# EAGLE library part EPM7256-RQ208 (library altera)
EPM7256E MAX 7000 family
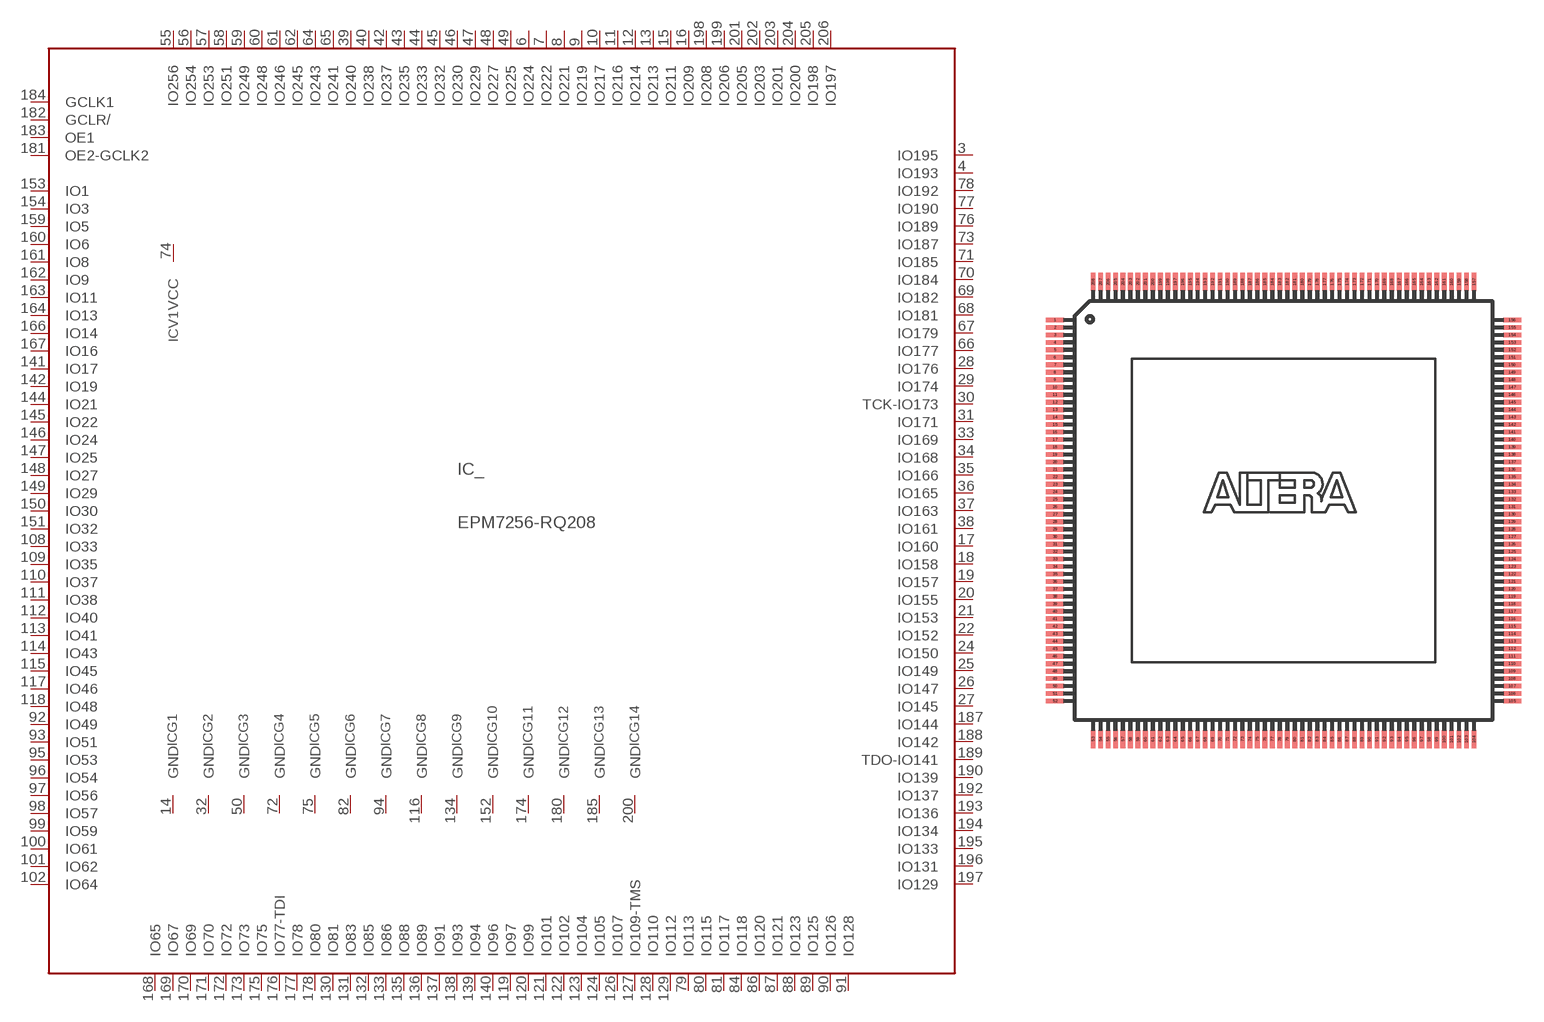
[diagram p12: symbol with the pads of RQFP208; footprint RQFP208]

Designator prefix IC; gates _=7256R208 G1=GND G2=GND G3=GND G4=GND G5=GND G6=GND G7=GND G8=GND G9=GND G10=GND G11=GND G12=GND G13=GND G14=GND V1=VCCINT V2=VCCINT V3=VCCINT V4=VCCINT VO1=VCCIO VO2=VCCIO VO3=VCCIO VO4=VCCIO VO5=VCCIO VO6=VCCIO VO7=VCCIO VO8=VCCIO VO9=VCCIO VO10=VCCIO NC1=NC NC2=NC NC3=NC NC4=NC NC5=NC NC6=NC NC7=NC NC8=NC NC9=NC NC10=NC NC11=NC NC12=NC NC13=NC NC14=NC NC15=NC NC16=NC

## EPM7256-RQ208 (MPN: EPM7256AEQC208-10N; OC_FARNELL: 1549440; OC_NEWARK: 51R9842)  [RQFP208]
1  NC1:NC  nc
2  NC2:NC  nc
3  _:IO195
4  _:IO193
5  VO1:VCCIO  pwr
6  _:IO224
7  _:IO222
8  _:IO221
9  _:IO219
10  _:IO217
11  _:IO216
12  _:IO214
13  _:IO213
14  G1:GND  pwr
15  _:IO211
16  _:IO209
17  _:IO160
18  _:IO158
19  _:IO157
20  _:IO155
21  _:IO153
22  _:IO152
23  VO2:VCCIO  pwr
24  _:IO150
25  _:IO149
26  _:IO147
27  _:IO145
28  _:IO176
29  _:IO174
30  _:TCK-IO173
31  _:IO171
32  G2:GND  pwr
33  _:IO169
34  _:IO168
35  _:IO166
36  _:IO165
37  _:IO163
38  _:IO161
39  _:IO240
40  _:IO238
41  VO3:VCCIO  pwr
42  _:IO237
43  _:IO235
44  _:IO233
45  _:IO232
46  _:IO230
47  _:IO229
48  _:IO227
49  _:IO225
50  G3:GND  pwr
51  NC3:NC  nc
52  NC4:NC  nc
53  NC5:NC  nc
54  NC6:NC  nc
55  _:IO256
56  _:IO254
57  _:IO253
58  _:IO251
59  _:IO249
60  _:IO248
61  _:IO246
62  _:IO245
63  VO4:VCCIO  pwr
64  _:IO243
65  _:IO241
66  _:IO177
67  _:IO179
68  _:IO181
69  _:IO182
70  _:IO184
71  _:IO185
72  G4:GND  pwr
73  _:IO187
74  V1:VCC  pwr
75  G5:GND  pwr
76  _:IO189
77  _:IO190
78  _:IO192
79  _:IO113
80  _:IO115
81  _:IO117
82  G6:GND  pwr
83  V2:VCC  pwr
84  _:IO118
85  VO5:VCCIO  pwr
86  _:IO120
87  _:IO121
88  _:IO123
89  _:IO125
90  _:IO126
91  _:IO128
92  _:IO49
93  _:IO51
94  G7:GND  pwr
95  _:IO53
96  _:IO54
97  _:IO56
98  _:IO57
99  _:IO59
100  _:IO61
101  _:IO62
102  _:IO64
103  NC7:NC  nc
104  NC8:NC  nc
105  NC9:NC  nc
106  NC10:NC  nc
107  VO6:VCCIO  pwr
108  _:IO33
109  _:IO35
110  _:IO37
111  _:IO38
112  _:IO40
113  _:IO41
114  _:IO43
115  _:IO45
116  G8:GND  pwr
117  _:IO46
118  _:IO48
119  _:IO97
120  _:IO99
121  _:IO101
122  _:IO102
123  _:IO104
124  _:IO105
125  VO7:VCCIO  pwr
126  _:IO107
127  _:IO109-TMS
128  _:IO110
129  _:IO112
130  _:IO81
131  _:IO83
132  _:IO85
133  _:IO86
134  G9:GND  pwr
135  _:IO88
136  _:IO89
137  _:IO91
138  _:IO93
139  _:IO94
140  _:IO96
141  _:IO17
142  _:IO19
143  VO8:VCCIO  pwr
144  _:IO21
145  _:IO22
146  _:IO24
147  _:IO25
148  _:IO27
149  _:IO29
150  _:IO30
151  _:IO32
152  G10:GND  pwr
153  _:IO1
154  _:IO3
155  NC11:NC  nc
156  NC12:NC  nc
157  NC13:NC  nc
158  NC14:NC  nc
159  _:IO5
160  _:IO6
161  _:IO8
162  _:IO9
163  _:IO11
164  _:IO13
165  VO9:VCCIO  pwr
166  _:IO14
167  _:IO16
168  _:IO65
169  _:IO67
170  _:IO69
171  _:IO70
172  _:IO72
173  _:IO73
174  G11:GND  pwr
175  _:IO75
176  _:IO77-TDI
177  _:IO78
178  _:IO80
179  V3:VCC  pwr
180  G12:GND  pwr
181  _:OE2-GCLK2  in
182  _:GCLR/  in
183  _:OE1  in
184  _:GCLK1  in
185  G13:GND  pwr
186  V4:VCC  pwr
187  _:IO144
188  _:IO142
189  _:TDO-IO141
190  _:IO139
191  VO10:VCCIO  pwr
192  _:IO137
193  _:IO136
194  _:IO134
195  _:IO133
196  _:IO131
197  _:IO129
198  _:IO208
199  _:IO206
200  G14:GND  pwr
201  _:IO205
202  _:IO203
203  _:IO201
204  _:IO200
205  _:IO198
206  _:IO197
207  NC15:NC  nc
208  NC16:NC  nc

## Footprint RQFP208 (pad centres in mm)
Power Quad Flat Pack
smd 1.2 x 0.32: 1 -15.3,12.75; 2 -15.3,12.25; 3 -15.3,11.75; 4 -15.3,11.25; 5 -15.3,10.75; 6 -15.3,10.25; 7 -15.3,9.75; 8 -15.3,9.25; 9 -15.3,8.75; 10 -15.3,8.25; 11 -15.3,7.75; 12 -15.3,7.25; 13 -15.3,6.75; 14 -15.3,6.25; 15 -15.3,5.75; 16 -15.3,5.25; 17 -15.3,4.75; 18 -15.3,4.25; 19 -15.3,3.75; 20 -15.3,3.25; 21 -15.3,2.75; 22 -15.3,2.25; 23 -15.3,1.75; 24 -15.3,1.25; 25 -15.3,0.75; 26 -15.3,0.25; 27 -15.3,-0.25; 28 -15.3,-0.75; 29 -15.3,-1.25; 30 -15.3,-1.75; 31 -15.3,-2.25; 32 -15.3,-2.75; 33 -15.3,-3.25; 34 -15.3,-3.75; 35 -15.3,-4.25; 36 -15.3,-4.75; 37 -15.3,-5.25; 38 -15.3,-5.75; 39 -15.3,-6.25; 40 -15.3,-6.75; 41 -15.3,-7.25; 42 -15.3,-7.75; 43 -15.3,-8.25; 44 -15.3,-8.75; 45 -15.3,-9.25; 46 -15.3,-9.75; 47 -15.3,-10.25; 48 -15.3,-10.75; 49 -15.3,-11.25; 50 -15.3,-11.75; 51 -15.3,-12.25; 52 -15.3,-12.75; 105 15.3,-12.75; 106 15.3,-12.25; 107 15.3,-11.75; 108 15.3,-11.25; 109 15.3,-10.75; 110 15.3,-10.25; 111 15.3,-9.75; 112 15.3,-9.25; 113 15.3,-8.75; 114 15.3,-8.25; 115 15.3,-7.75; 116 15.3,-7.25; 117 15.3,-6.75; 118 15.3,-6.25; 119 15.3,-5.75; 120 15.3,-5.25; 121 15.3,-4.75; 122 15.3,-4.25; 123 15.3,-3.75; 124 15.3,-3.25; 125 15.3,-2.75; 126 15.3,-2.25; 127 15.3,-1.75; 128 15.3,-1.25; 129 15.3,-0.75; 130 15.3,-0.25; 131 15.3,0.25; 132 15.3,0.75; 133 15.3,1.25; 134 15.3,1.75; 135 15.3,2.25; 136 15.3,2.75; 137 15.3,3.25; 138 15.3,3.75; 139 15.3,4.25; 140 15.3,4.75; 141 15.3,5.25; 142 15.3,5.75; 143 15.3,6.25; 144 15.3,6.75; 145 15.3,7.25; 146 15.3,7.75; 147 15.3,8.25; 148 15.3,8.75; 149 15.3,9.25; 150 15.3,9.75; 151 15.3,10.25; 152 15.3,10.75; 153 15.3,11.25; 154 15.3,11.75; 155 15.3,12.25; 156 15.3,12.75
smd 0.32 x 1.2: 53 -12.75,-15.3; 54 -12.25,-15.3; 55 -11.75,-15.3; 56 -11.25,-15.3; 57 -10.75,-15.3; 58 -10.25,-15.3; 59 -9.75,-15.3; 60 -9.25,-15.3; 61 -8.75,-15.3; 62 -8.25,-15.3; 63 -7.75,-15.3; 64 -7.25,-15.3; 65 -6.75,-15.3; 66 -6.25,-15.3; 67 -5.75,-15.3; 68 -5.25,-15.3; 69 -4.75,-15.3; 70 -4.25,-15.3; 71 -3.75,-15.3; 72 -3.25,-15.3; 73 -2.75,-15.3; 74 -2.25,-15.3; 75 -1.75,-15.3; 76 -1.25,-15.3; 77 -0.75,-15.3; 78 -0.25,-15.3; 79 0.25,-15.3; 80 0.75,-15.3; 81 1.25,-15.3; 82 1.75,-15.3; 83 2.25,-15.3; 84 2.75,-15.3; 85 3.25,-15.3; 86 3.75,-15.3; 87 4.25,-15.3; 88 4.75,-15.3; 89 5.25,-15.3; 90 5.75,-15.3; 91 6.25,-15.3; 92 6.75,-15.3; 93 7.25,-15.3; 94 7.75,-15.3; 95 8.25,-15.3; 96 8.75,-15.3; 97 9.25,-15.3; 98 9.75,-15.3; 99 10.25,-15.3; 100 10.75,-15.3; 101 11.25,-15.3; 102 11.75,-15.3; 103 12.25,-15.3; 104 12.75,-15.3; 157 12.75,15.3; 158 12.25,15.3; 159 11.75,15.3; 160 11.25,15.3; 161 10.75,15.3; 162 10.25,15.3; 163 9.75,15.3; 164 9.25,15.3; 165 8.75,15.3; 166 8.25,15.3; 167 7.75,15.3; 168 7.25,15.3; 169 6.75,15.3; 170 6.25,15.3; 171 5.75,15.3; 172 5.25,15.3; 173 4.75,15.3; 174 4.25,15.3; 175 3.75,15.3; 176 3.25,15.3; 177 2.75,15.3; 178 2.25,15.3; 179 1.75,15.3; 180 1.25,15.3; 181 0.75,15.3; 182 0.25,15.3; 183 -0.25,15.3; 184 -0.75,15.3; 185 -1.25,15.3; 186 -1.75,15.3; 187 -2.25,15.3; 188 -2.75,15.3; 189 -3.25,15.3; 190 -3.75,15.3; 191 -4.25,15.3; 192 -4.75,15.3; 193 -5.25,15.3; 194 -5.75,15.3; 195 -6.25,15.3; 196 -6.75,15.3; 197 -7.25,15.3; 198 -7.75,15.3; 199 -8.25,15.3; 200 -8.75,15.3; 201 -9.25,15.3; 202 -9.75,15.3; 203 -10.25,15.3; 204 -10.75,15.3; 205 -11.25,15.3; 206 -11.75,15.3; 207 -12.25,15.3; 208 -12.75,15.3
